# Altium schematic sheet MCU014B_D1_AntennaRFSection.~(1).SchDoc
size 431 x 279 mm; Date: Not shown in title block; ApprovedBy: Not shown in title block; CheckedBy: Not shown in title block; Author: Not shown in title block; CompanyName: Not shown in title block; DrawnBy: Vince Rodriguez; Engineer: Vince Rodriguez; Organization: Not shown in title block; Address1: Not shown in title block; Address2: Not shown in title block; Address3: Not shown in title block; Address4: Not shown in title block; DocumentNumber: 6; Revision: Use project parameter SCH_Rev; SheetNumber: 6; SheetTotal: 7; PageSetup: Record=PageOptions¦CenterHorizontal=True¦CenterVertical=True¦PrintScale=1.00¦XCorrection=1.00¦YCorrection=1.00¦PrintKind=0¦BorderSize=5000000¦LeftOffset=0¦BottomOffset=0¦Orientation=2¦PaperLength=1000¦PaperWidth=1000¦Scale=100¦PaperSource=15¦PrintQuality=600¦MediaType=1¦DitherType=10¦PaperKind=Letter¦PrintScaleMode=1
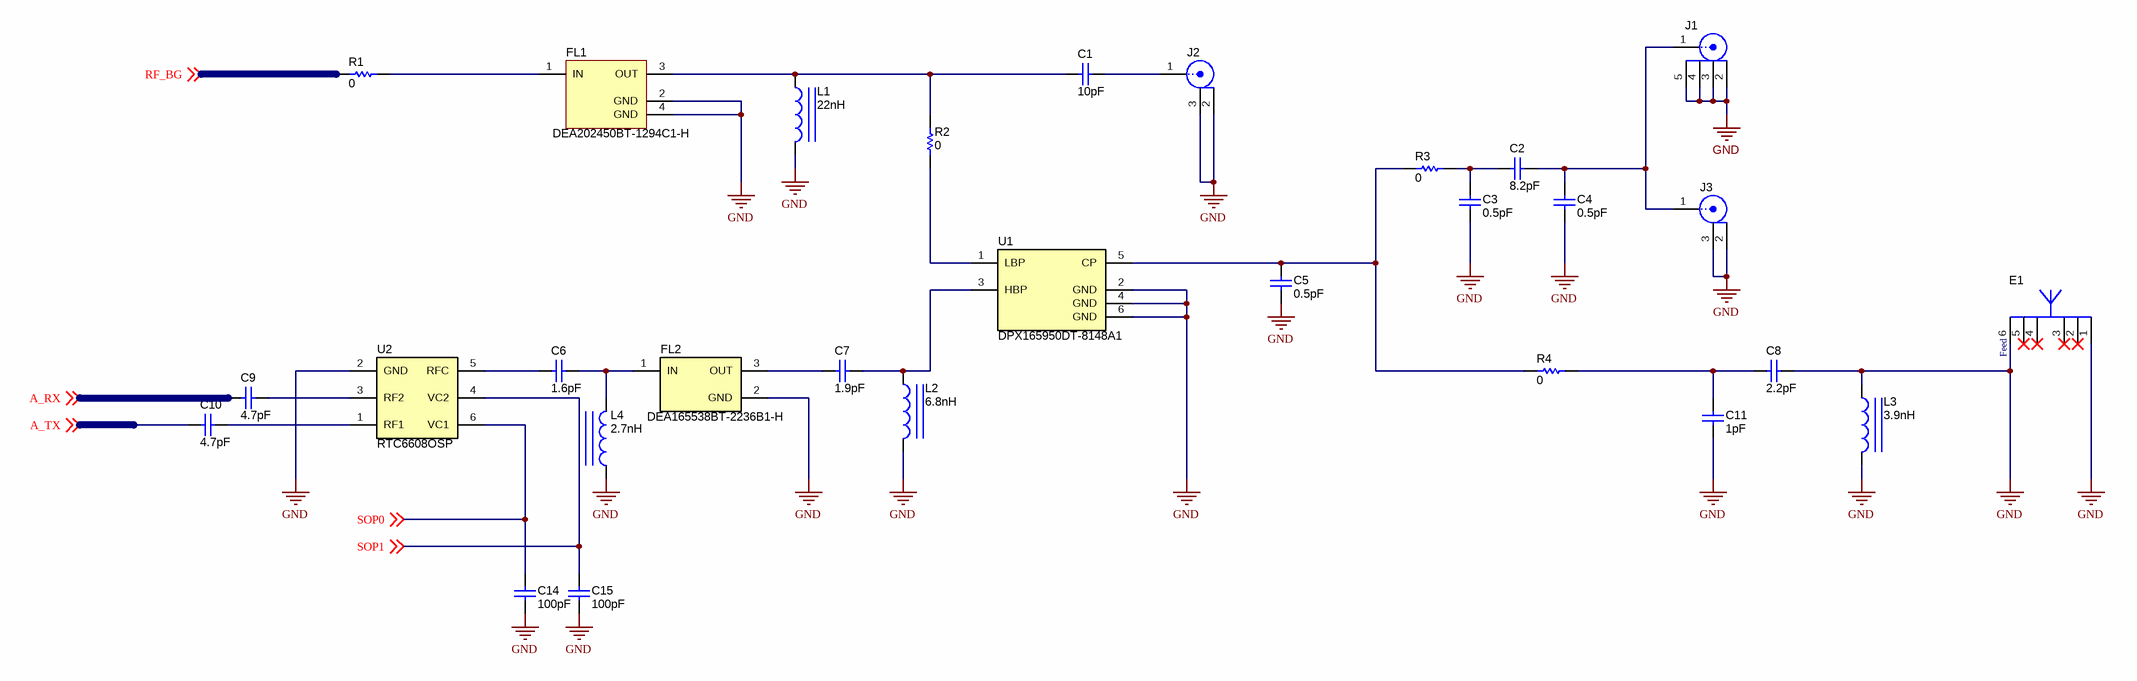
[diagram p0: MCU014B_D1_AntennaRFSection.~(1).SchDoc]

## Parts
C1  ValueDisplayed: 10pF  [0402S]  (hidden comment: CMP-0006408-2)
C2  ValueDisplayed: 8.2pF  [0402S]  (hidden comment: 0402N8R2C500CT)
C3  ValueDisplayed: 0.5pF  [0402S]  (hidden comment: GJM1555C1HR50BB01J)
C4  ValueDisplayed: 0.5pF  [0402S]  (hidden comment: GJM1555C1HR50BB01J)
C5  ValueDisplayed: 0.5pF  [0402S]  (hidden comment: GJM1555C1HR50BB01J)
C6  ValueDisplayed: 1.6pF  [0201_033]  (hidden comment: GRM0335C1H1R6BA01D)
C7  ValueDisplayed: 1.9pF  [0402S]  (hidden comment: GJM1555C1H1R9WB01D)
C8  ValueDisplayed: 2.2pF  [0402S]  (hidden comment: GJM1555C1H2R2BB01D)
C9  ValueDisplayed: 4.7pF  [0201_033]  (hidden comment: GRM0335C1H4R7BA01D)
C10  ValueDisplayed: 4.7pF  [0201_033]  (hidden comment: GRM0335C1H4R7BA01D)
C11  ValueDisplayed: 1pF  [0402S]  (hidden comment: CMP-0006426-2)
C14  ValueDisplayed: 100pF  [0201]  (hidden comment: CC0201JRNPO8BN101)
C15  ValueDisplayed: 100pF  [0201]  (hidden comment: CC0201JRNPO8BN101)
E1  CMP-0001857-1  [Ethertronics_M830520]  (value not drawn)
FL1  PartNumber: DEA202450BT-1294C1-H  [TDK_DEA202450BT-1294C1-H]  (hidden comment: CMP-0002039-2)
FL2  PartNumber: DEA165538BT-2236B1-H  [TDK_DEA165538BT-2236B1-H]  (hidden comment: CMP-0002038-2)
J1  CMP-0055832-1  [Hustsan_SMA-10V21-TGG]  (value not drawn)
J2  U.FL-R-SMT-1(01)  [CONN_UFL-R-SMT-1]  (value not drawn)
J3  U.FL-R-SMT-1(01)  [CONN_UFL-R-SMT-1]  (value not drawn)
L1  ValueDisplayed: 22nH  [0402S]  (hidden comment: LQG15HZ22NH02D)
L2  ValueDisplayed: 6.8nH  [0402S]  (hidden comment: LQG15HZ6N8H02D)
L3  ValueDisplayed: 3.9nH  [0402S]  (hidden comment: CMP-0058633-2)
L4  ValueDisplayed: 2.7nH  [0402S]  (hidden comment: LQG15WH2N7C02D)
R1  ValueDisplayed: 0  [0201]  (hidden comment: CRCW02010000Z0ED)
R2  ValueDisplayed: 0  [0402S]  (hidden comment: CMP-0026992-2)
R3  ValueDisplayed: 0  [0402S]  (hidden comment: CMP-0026992-2)
R4  ValueDisplayed: 0  [0402S]  (hidden comment: CMP-0026992-2)
U1  PartNumber: DPX165950DT-8148A1  [TDK_DPX165950DT-8148A1]  (hidden comment: CMP-0002040-1)
U2  RTC6608OSP  [Richwave_RTC6608OSP]

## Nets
GND: C3.2 C4.2 C5.2 C8.2 C11.2 C14.2 C15.2 E1.1(Feed) E1.6 FL1.2(GND) FL1.4(GND) FL2.2(GND) J1.2 J1.3 J1.4 J1.5 J2.2 J2.3 J3.2 J3.3 L1.2 L2.2 L3.1 L3.2 L4.1 U1.2(GND) U1.4(GND) U1.6(GND) U2.2(GND)
A_RX: C9.2 ; off-sheet A_RX
A_TX: C10.2 ; off-sheet A_TX
RF_BG: R1.2 ; off-sheet RF_BG
SOP0: C14.1 U2.6(VC1) ; off-sheet SOP0
SOP1: C15.1 U2.4(VC2) ; off-sheet SOP1
NetC1_1: C1.1 FL1.3(OUT) L1.1 R2.2
NetC1_2: C1.2 J2.1
NetC2_1: C2.1 C3.1 R3.2
NetC2_2: C2.2 C4.1 J1.1 J3.1
NetC5_1: C5.1 R3.1 R4.1 U1.5(CP)
NetC6_1: C6.1 FL2.1(IN) L4.2
NetC6_2: C6.2 U2.5(RFC)
NetC7_1: C7.1 FL2.3(OUT)
NetC7_2: C7.2 L2.1 U1.3(HBP)
NetC8_1: C8.1 C11.1 R4.2
NetC9_1: C9.1 U2.3(RF2)
NetC10_1: C10.1 U2.1(RF1)
NetFL1_1: FL1.1(IN) R1.1
NetR2_1: R2.1 U1.1(LBP)

Not connected (* = marked no-connect by the designer): E1 2(GND)* 3(GND)* 4(Feed)* 5*

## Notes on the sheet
- (near E1) Feed

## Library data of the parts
C1 = CMP-0006408-2: CAP, CERM, 10 pF, 50 V, +/- 5%, C0G/NP0, 0402; PartNumber: GRM1555C1H100JA01D; Manufacturer: MuRata; Alternate Manufacturer: ----; Polarized: N; CompType: Capacitor; Value: 10pF; U/M: EA; Value1: Unknown; VDC_V: 50V; TaMin_C: -55°C; TaMax_C: 125°C; Cap_Case: 0402; SizeAreaWB_mm2: 3; SizeZ_mm: 0.6; SizeX_mm: 1; SizeY_mm: 0.5; AEC Category: Q200
C2 = CMP-0085845-1: CAP, CERM, 8.2 pF, 50 V,+/- 3%, C0G/NP0, 0402; Manufacturer: Walsin; Alternate PartNumber: GRM1555C1H8R2CA01D; Alternate Manufacturer: MuRata; Polarized: N; Value: 8.2pF; U/M: EA; VDC_V: 50V; TaMin_C: -55°C; TaMax_C: 125°C; Cap_Case: 0402; SizeArea_mm2: 0.5; SizeAreaWB_mm2: 3; SizeX_mm: 1; SizeZ_mm: 0.6; AEC Category: Q200
C3-C5 = CMP-0080073-1: CAP, CERM, 0.5 pF, 50 V,+/- 20%, C0G/NP0, 0402; Manufacturer: MuRata; Polarized: N; Value: 0.5pF; U/M: EA; VDC_V: 50V; TaMin_C: -55°C; TaMax_C: 125°C; Cap_Case: 0402; Green_Lifecycle: Active; SizeAreaWB_mm2: 3; Green_REACh: Passed; SizeZ_mm: 0.6; SizeX_mm: 1; SizeY_mm: 0.5; AEC Category: Q200
C6 = CMP-0080075-1: CAP, CERM, 1.6 pF, 50 V,+/- 7%, C0G/NP0, 0201; Manufacturer: MuRata; Polarized: N; Value: 1.6pF; U/M: EA; VDC_V: 50V; TaMin_C: -55°C; TaMax_C: 125°C; Cap_Case: 0201; SizeArea_mm2: 0.18; SizeAreaWB_mm2: 2.08; SizeX_mm: 0.6; SizeY_mm: 0.3; SizeZ_mm: 0.33; AEC Category: Q200
C7 = CMP-0085853-1: CAP, CERM, 1.9 pF, 50 V,+/- 2.6%, C0G/NP0, 0402; Manufacturer: MuRata; Alternate PartNumber: GRM1555C1H1R9WA01D; Polarized: N; Value: 1.9pF; U/M: EA; VDC_V: 50V; TaMin_C: -55°C; TaMax_C: 125°C; Cap_Case: 0402; SizeArea_mm2: 0.5; SizeAreaWB_mm2: 3; SizeX_mm: 1; SizeZ_mm: 0.6; AEC Category: Q200
C8 = CMP-0085854-1: CAP, CERM, 2.2 pF, 50 V,+/- 4.5%, C0G/NP0, 0402; Manufacturer: MuRata; Alternate PartNumber: GRM1555C1H2R2BA01D; Polarized: N; Value: 2.2pF; U/M: EA; VDC_V: 50V; TaMin_C: -55°C; TaMax_C: 125°C; Cap_Case: 0402; SizeArea_mm2: 0.5; SizeAreaWB_mm2: 3; SizeX_mm: 1; SizeZ_mm: 0.6; AEC Category: Q200
C9 C10 = CMP-0080076-1: CAP, CERM, 4.7 pF, 50 V,+/- 3%, C0G/NP0, 0201; Manufacturer: MuRata; Polarized: N; Value: 4.7pF; U/M: EA; VDC_V: 50V; TaMin_C: -55°C; TaMax_C: 125°C; Cap_Case: 0201; SizeArea_mm2: 0.18; SizeAreaWB_mm2: 2.08; SizeX_mm: 0.6; SizeY_mm: 0.3; SizeZ_mm: 0.33; AEC Category: Q200
C11 = CMP-0006426-2: CAP, CERM, 1 pF, 50 V, +/- 10%, C0G/NP0, 0402; PartNumber: GRM1555C1H1R0BA01D; Manufacturer: MuRata; Alternate PartNumber: ----; Polarized: N; CompType: Capacitor; Value: 1pF; U/M: EA; Value1: Unknown; VDC_V: 50V; TaMin_C: -55°C; TaMax_C: 125°C; Cap_Case: 0402; SizeAreaWB_mm2: 3; SizeZ_mm: 0.6; SizeX_mm: 1; SizeY_mm: 0.5; AEC Category: Q200
C14 C15 = CMP-0085847-1: CAP, CERM, 100 pF, 25 V,+/- 5%, C0G/NP0, 0201; Manufacturer: Yageo; Alternate PartNumber: C0603C0G1E101J030BA; Polarized: N; Value: 100pF; U/M: EA; VDC_V: 25V; TaMin_C: -55°C; TaMax_C: 125°C; SizeArea_mm2: 0.18; SizeAreaWB_mm2: 2.08; SizeX_mm: 0.6; SizeY_mm: 0.3; SizeZ_mm: 0.26; AEC Category: Q200
E1 = CMP-0001857-1: WLAN ANTENNA 802.11, SMD; PartNumber: M830520; Manufacturer: Ethertronics; Alternate Manufacturer: ----; SizeAreaWB_mm2: 50; SizeArea_mm2: 24; SizeX_mm: 3; SizeY_mm: 8; SizeZ_mm: 1.33
FL1 = CMP-0002039-2: Multilayer Chip Band Pass Filter For 2.4GHz W-LAN/Bluetooth, SMD; Manufacturer: TDK; Alternate Manufacturer: ----; Value: 1.02 dB
FL2 = CMP-0002038-2: Multilayer Band Pass Filter For 5GHz W-LAN/LTE-U; Manufacturer: TDK; Alternate Manufacturer: ----; SizeAreaWB_mm2: 4.68; SizeArea_mm2: 1.28; SizeX_mm: 1.6; SizeY_mm: 0.8; SizeZ_mm: 0.65
J1 = CMP-0055832-1: Connector, SMA, Vertical, Gold, SMT; PartNumber: SMA-10V21-TGG; Manufacturer: Hus-Tsan Group Co., Ltd.; Alternate Manufacturer: 傲创; Alternate PartNumber: SMA-050710; CT: TRUE; CNHeader: FALSE
J2 J3 = CMP-0075320-1: Receptacle, Ultra Miniature Coaxial, Male Pin, 50 ohm, SMT; Manufacturer: Hirose Electric Co. Ltd.; Alternate Manufacturer: ----; CNHeader: False; Gender: Female; ContactFinish: Gold
L1 = CMP-0080371-1: Inductor, Multilayer, Air Core, 22 nH, 0.35 A, 0.42 ohm, AEC-Q200 Grade 1, SMD; Manufacturer: MuRata; Value: 22nH; Imax_A: 350mA; Irms: 0.35A @ 25C rise; DCR_ohm: 0.42; Value2: 0.35A; SizeAreaWB_mm2: 3; SizeZ_mm: 0.55; SizeX_mm: 1; SizeY_mm: 0.5; AEC Qualified: Y; AEC Category: Q200
L2 = CMP-0080372-1: Inductor, Multilayer, Air Core, 6.8 nH, 0.6 A, 0.22 ohm, AEC-Q200 Grade 1, SMD; Manufacturer: MuRata; Value: 6.8nH; Imax_A: 600mA; Irms: 0.6A @ 25C rise; DCR_ohm: 0.22; Value2: 0.6A; SizeAreaWB_mm2: 3; SizeZ_mm: 0.55; SizeX_mm: 1; SizeY_mm: 0.5; AEC Qualified: Y; AEC Category: Q200
L3 = CMP-0058633-2: Inductor, Multilayer, Air Core, 3.9 nH, 0.75 A, 0.14 ohm, SMD; PartNumber: LQG15HS3N9S02D; Manufacturer: MuRata; Value: 3.9nH; Imax_A: 750mA; Irms: 0.75A @ 25C rise; DCR_ohm: 0.14; Value2: 0.75A; Green_Lifecycle: Active; SizeAreaWB_mm2: 3; Green_REACh: Passed; SizeZ_mm: 0.55; SizeX_mm: 1; SizeY_mm: 0.5; AEC Qualified: N; AEC Category: Q200
L4 = CMP-0080374-1: Inductor, Multilayer, Air Core, 2.7 nH, 0.9 A, 0.07 ohm, AEC-Q200 Grade 1, SMD; Manufacturer: MuRata; Value: 2.7nH; Imax_A: 900mA; Irms: 0.9A @ 25C rise; DCR_ohm: 0.07; Value2: 0.9A; SizeAreaWB_mm2: 3.2; SizeZ_mm: 0.6; SizeX_mm: 1; AEC Qualified: Y; AEC Category: Q200
R1 = CMP-0027008-4: RES, 0, 5%, 0.05 W, 0201; Manufacturer: Vishay-Dale; Value: 0; Value_Code: 0000; Power_W: 50mW; Value2: 0.05W; TempCo: ppm/C; SizeArea_mm2: 0.18; SizeX_mm: 0.6; SizeY_mm: 0.3; SizeZ_mm: 0.26; EIA_Code: E24; AEC Category: Q200; AEC Qualified: N
R2-R4 = CMP-0026992-2: RES, 0, 5%, 0.063 W, 0402; PartNumber: ERJ-2GE0R00X; Manufacturer: Panasonic; Alternate Manufacturer: YAGEO; Alternate PartNumber: RC0402JR-070RL; CompType: Resistor; Value: 0; Value_Code: 0000; Power_W: 63mW; Value2: 0.063W; VDC_V: 50V; TempCo: 600 ppm/C; SizeArea_mm2: 0.5; SizeX_mm: 1; SizeZ_mm: 0.6; EIA_Code: E24; U/M: EA; AEC Category: Q200
U1 = CMP-0002040-1: Multilayer Diplexer for 2.4GHz W-LAN & Bluetooth / 5GHz W-LAN; Manufacturer: TDK; Alternate Manufacturer: ----; SizeAreaWB_mm2: 4.68; SizeArea_mm2: 1.28; SizeX_mm: 0.8; SizeY_mm: 1.6; SizeZ_mm: 0.7
U2 = CMP-0065464-1: 0.03 GHz-6 GHz SPDT Switch; Manufacturer: Richwave; Alternate Manufacturer: ----; Alternate PartNumber: Order Directly from Richwave; SizeAreaWB_mm2: 4.0; SizeArea_mm2: 1.0; SizeZ_mm: 0.4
